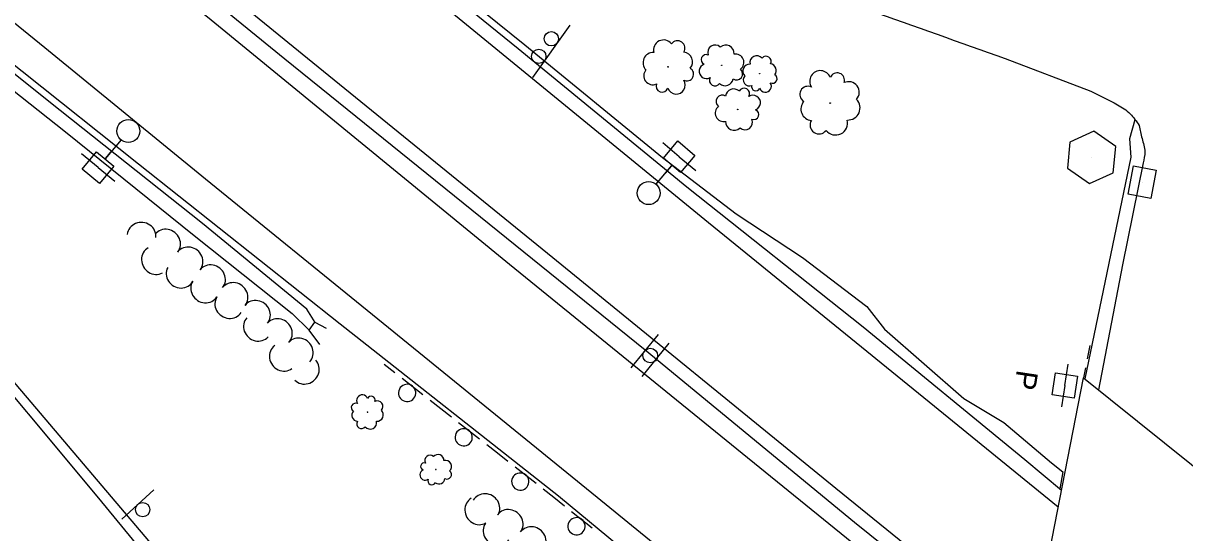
# Model space of a CAD drawing. Extents: x 1746010 to 1754829, y 655801 to 663091.
# Drawn here: x 1748666.3 to 1749070.2, y 661182.3 to 661359.7 of the extents above; entities that cross this region are included whole.
import ezdxf

# ---------------------------------------------------------------- set-up
doc = ezdxf.new("R2010")
doc.units = 0
for name, color, linetype in [('SURVEY - AERIAL SURVEY - Photo Control - Points - Elevations', 7, 'Continuous'), ('SURVEY - AERIAL SURVEY - Photo Control - Points - Locators', 7, 'Continuous'), ('SURVEY - AERIAL SURVEY - Photo Control - Points - Numbers', 7, 'Continuous'), ('SURVEY - AERIAL SURVEY - Photo Control with Text', 7, 'Continuous'), ('SURVEY - CENTERLINE - Existing Roads Curve Text', 7, 'Continuous'), ('SURVEY - CENTERLINE - Existing Roads Text', 7, 'Continuous'), ('SURVEY - CENTERLINE - Preliminary - Development', 7, 'Continuous')]:
    doc.layers.add(name, color=color, linetype=linetype)

msp = doc.modelspace()

# ---------------------------------------------------------------- linework, layer by layer
at = {"layer": 'SURVEY - AERIAL SURVEY - Photo Control - Points - Elevations'}
for points in [[(1748713.37, 661453.65), (1748716.55, 661453.81), (1748746.53, 661428.67), (1748797.36, 661387.23), (1748840.72, 661352.13), (1748888.64, 661312.91), (1748914.18, 661293.34), (1748937.25, 661278.19), (1748959.67, 661261.1), (1748965.83, 661253.19), (1748993.44, 661229.06), (1749007.32, 661220.73), (1749023.86, 661206.7), (1749027.85, 661203.6), (1749026.76, 661197.6)], [(1748767.81, 661255.54), (1748764.9, 661260.11), (1748728.66, 661289.97), (1748679.17, 661329.29), (1748636.92, 661363.04), (1748593.63, 661396.59), (1748567.91, 661416.28), (1748565.84, 661413.35), (1748621.69, 661369.01), (1748680.97, 661321.93), (1748725.75, 661285.75), (1748759.81, 661258.65), (1748765.74, 661252.81)], [(1748769.51, 661247.87), (1748765.74, 661252.81), (1748767.69, 661255.6), (1748771.63, 661253.55)], [(1749091.38, 661191), (1749050.62, 660981.19), (1748994.11, 661026.26), (1749035.04, 661236.3)], [(1749035.04, 661236.3), (1749091.38, 661191)]]:
    msp.add_lwpolyline(points, dxfattribs=at)
at = {"layer": 'SURVEY - AERIAL SURVEY - Photo Control - Points - Locators'}
for points in [[(1749014.37, 661130.26), (1748990.7, 661149.54), (1748916.31, 661209.97), (1748835.38, 661275.76), (1748731.71, 661360.72), (1748655.6, 661422.38), (1748555.07, 661504.4), (1748459.33, 661582.61), (1748380.29, 661646.59), (1748288.83, 661717.68), (1748181.12, 661800.02), (1748091.36, 661866.45), (1748036.84, 661905.72)], [(1749004.96, 661081.96), (1748990.07, 661094.14), (1748934.34, 661138.81), (1748865.88, 661194.6), (1748789.64, 661256.64), (1748729.69, 661305.4), (1748673.84, 661351.11), (1748595.91, 661414.43), (1748530.55, 661467.92), (1748473.83, 661514.17), (1748421, 661557.21), (1748361.81, 661604.95), (1748313.62, 661643.08), (1748341.85, 661611.66), (1748371.26, 661577.05), (1748408.51, 661529.92)], [(1749002.83, 661071), (1748965.52, 661101.51), (1748852.49, 661195.09), (1748776.59, 661254.93), (1748706.42, 661310.6), (1748625.44, 661375.29), (1748570.62, 661419.8), (1748495.86, 661480.71), (1748433.37, 661530.35), (1748414.07, 661545.49), (1748413.71, 661545.75)], [(1748406.97, 661541.06), (1748446.41, 661490.26), (1748508.74, 661414.72), (1748569.86, 661344.49), (1748590.82, 661319.8), (1748726.77, 661159.53), (1748751.93, 661128.01), (1748766.95, 661111.05), (1748766.91, 661110.24)], [(1748523.79, 661544.26), (1748587.7, 661492.34), (1748672.29, 661423.24), (1748765.2, 661347.55), (1748850.45, 661278.14), (1748948.94, 661197.9), (1749016.8, 661142.7)], [(1749026.26, 661191.27), (1748981.31, 661227.83), (1748904.63, 661290.22), (1748803.87, 661372.8), (1748715.15, 661444.7), (1748642.21, 661503.71), (1748667.72, 661487.53), (1748715.24, 661463.43)], [(1749027.39, 661197.07), (1749014.65, 661207.7), (1748958.39, 661253.89), (1748897.1, 661302.67), (1748838.46, 661350.81), (1748788.42, 661391.33), (1748735.2, 661434.76), (1748714.24, 661451.33), (1748713.32, 661453.39), (1748714.02, 661456.96), (1748716.26, 661459.11), (1748720.91, 661460.82)], [(1748543.22, 661365.16), (1748594.47, 661308.59), (1748642.89, 661253.78), (1748692.5, 661194.4), (1748742.62, 661133.3)], [(1749007.79, 661347.35), (1749037.51, 661336.03)], [(1749052.83, 661326.1), (1749050.99, 661319.39), (1749051.52, 661313.03), (1749035.46, 661235.96)], [(1749055.75, 661311.05), (1749048.62, 661275.6), (1749040.22, 661232.14)]]:
    msp.add_lwpolyline(points, dxfattribs=at)
for points in [[(1748715.24, 661463.43), (1748765.05, 661440.48), (1748816.14, 661417.66), (1748863.57, 661398.48), (1748914.39, 661379.98), (1748960.41, 661364.19), (1749007.79, 661347.35)], [(1749037.51, 661336.03), (1749046.79, 661331.31), (1749051.24, 661328.17), (1749054.38, 661324.09)], [(1749054.38, 661324.09), (1749055.37, 661319.56), (1749056.33, 661314.9), (1749055.75, 661311.05)]]:
    msp.add_spline(points, degree=3, dxfattribs=at)
at = {"layer": 'SURVEY - AERIAL SURVEY - Photo Control - Points - Numbers'}
for points in [[(1748040.01, 661910.33), (1748122.02, 661850.78), (1748195.38, 661796.53), (1748267.56, 661741.32), (1748333.52, 661690.82), (1748402.34, 661636.08), (1748451.04, 661597.23), (1748504.04, 661553.85), (1748559.78, 661508.8), (1748636.39, 661445.77), (1748709.27, 661386.44), (1748757.29, 661347.34), (1748822.35, 661294.7), (1748882.58, 661246), (1748955.33, 661186.03), (1749015.15, 661137.9)], [(1749037.18, 661247.5), (1749036.29, 661242.88)], [(1748791.87, 661241.03), (1748795.56, 661238.12)], [(1749035.69, 661239.74), (1749035.04, 661236.3)], [(1748798.08, 661236.15), (1748805.32, 661230.47)], [(1748807.83, 661228.49), (1748811.53, 661225.59)], [(1748811.53, 661225.59), (1748815.23, 661222.69)], [(1748817.74, 661220.71), (1748824.98, 661215.03)], [(1748827.5, 661213.06), (1748831.19, 661210.16)], [(1748831.19, 661210.16), (1748834.89, 661207.25)], [(1748837.41, 661205.28), (1748844.64, 661199.6)], [(1748847.16, 661197.62), (1748850.83, 661194.69)], [(1748850.83, 661194.69), (1748854.51, 661191.76)], [(1748857.01, 661189.77), (1748864.2, 661184.03)]]:
    msp.add_lwpolyline(points, dxfattribs=at)
for centre, start, end in [((1748799.82, 661231.01), 164.9095, 164.8956), ((1748819.49, 661215.57), 164.9095, 164.8956), ((1748839.15, 661200.14), 164.9095, 164.8956), ((1748858.71, 661184.61), 164.4875, 164.4736)]:
    msp.add_arc(centre, 3, start, end, dxfattribs=at)
at = {"layer": 'SURVEY - AERIAL SURVEY - Photo Control with Text'}
for p, q in [((1748856.42, 661359.05), (1748843.38, 661340.83)), ((1749037.77, 661312.94), (1749037.77, 661312.94)), ((1748877.78, 661239.73), (1748887.27, 661251.34)), ((1748881.5, 661236.69), (1748890.99, 661248.31)), ((1748700.64, 661187.12), (1748711.72, 661197.23))]:
    msp.add_line(p, q, dxfattribs=at)
msp.add_lwpolyline([(1749038.62, 661322.13), (1749030.25, 661318.24), (1749029.51, 661309.22), (1749037.11, 661303.86), (1749045.29, 661307.64), (1749046.22, 661316.77), (1749038.62, 661322.13)], dxfattribs=at)
for centre, radius in [((1748849.97, 661354.26), 2.5), ((1748845.61, 661348.15), 2.5), ((1748884.38, 661244.02), 2.54), ((1748707.86, 661190.39), 2.5)]:
    msp.add_circle(centre, radius, dxfattribs=at)
at = {"layer": 'SURVEY - CENTERLINE - Existing Roads Curve Text'}
for p, q in [((1748700.39, 661319.14), (1748694.85, 661312.43)), ((1748692.36, 661309.42), (1748686.58, 661314.2)), ((1748695.1, 661312.74), (1748697.14, 661315.21)), ((1748894.42, 661313.19), (1748888.68, 661318.01)), ((1748886.32, 661303.54), (1748891.91, 661310.2)), ((1748894.42, 661313.19), (1748900.17, 661308.37)), ((1748692.36, 661309.42), (1748698.15, 661304.65)), ((1748891.66, 661309.9), (1748889.6, 661307.45)), ((1749028.51, 661233.6), (1749029.63, 661241.02)), ((1749028.51, 661233.6), (1749027.38, 661226.19))]:
    msp.add_line(p, q, dxfattribs=at)
for points in [[(1748899.92, 661313.67), (1748894.9, 661307.69), (1748888.93, 661312.71), (1748893.94, 661318.69)], [(1748686.87, 661308.9), (1748691.84, 661314.92), (1748697.86, 661309.95), (1748692.89, 661303.93)], [(1749032.95, 661236.88), (1749031.78, 661229.16), (1749024.07, 661230.33), (1749025.24, 661238.04)]]:
    msp.add_lwpolyline(points, close=True, dxfattribs=at)
for centre in [(1748702.87, 661322.15), (1748883.81, 661300.55)]:
    msp.add_circle(centre, 4, dxfattribs=at)
at = {"layer": 'SURVEY - CENTERLINE - Existing Roads Text'}
for centre, radius in [((1748890.56, 661344.51), 0.109), ((1748909.23, 661345.03), 0.0891), ((1748922.44, 661342.08), 0.0734), ((1748946.94, 661331.89), 0.129), ((1748914.76, 661329.66), 0.0907), ((1748786.03, 661224.32), 0.0688), ((1748809.8, 661204.35), 0.0645)]:
    msp.add_circle(centre, radius, dxfattribs=at)
for centre, radius, start, end in [((1748888.98, 661350.33), 3.52, 38.1082, 193.9467), ((1748893.84, 661350.95), 2.6, 328.3611, 143.3613), ((1748906.9, 661349.56), 2.55, 45.0405, 201.8294), ((1748910.63, 661349.2), 2.91, 354.0933, 131.6175), ((1748885.39, 661345.94), 3.55, 87.2123, 224.7366), ((1748895.76, 661346.25), 3.35, 318.2022, 85.0478), ((1748903.84, 661347), 1.75, 67.1567, 245.9023), ((1748914.06, 661346.06), 2.89, 304.9891, 100.8276), ((1748921.37, 661346.01), 2.38, 38.1082, 193.9467), ((1748924.65, 661346.43), 1.76, 328.3611, 143.3613), ((1748885.19, 661341.37), 3.11, 138.1596, 294.9485), ((1748897.08, 661341.97), 2.36, 242.9151, 60.2343), ((1748903.88, 661342.96), 2.55, 107.1774, 300.5971), ((1748914.36, 661342.05), 2.13, 235.242, 50.2423), ((1748918.94, 661343.04), 2.4, 87.2123, 224.7366), ((1748925.95, 661343.26), 2.26, 318.2022, 85.0478), ((1748943.53, 661339.48), 3.7, 20.2964, 213.7161), ((1748949.37, 661339.85), 2.54, 340.2758, 159.0214), ((1748888.51, 661337.83), 2.14, 160.2758, 339.0214), ((1748893.42, 661338.14), 3.11, 200.2964, 33.7161), ((1748906.85, 661339.79), 1.94, 149.796, 327.1152), ((1748910.42, 661340.69), 2.75, 225.0831, 351.9288), ((1748918.81, 661339.96), 2.1, 138.1596, 294.9485), ((1748924.37, 661337.77), 2.1, 200.2964, 33.7161), ((1748926.85, 661340.36), 1.6, 242.9151, 60.2343), ((1748953.33, 661335.63), 3.71, 318.1596, 114.9485), ((1748909.41, 661332.46), 2.17, 57.8058, 232.806), ((1748913.35, 661334.02), 2.8, 47.6469, 174.4925), ((1748916.94, 661335.09), 1.97, 332.3598, 149.679), ((1748920.1, 661332.01), 2.59, 289.7411, 123.1608), ((1748921.05, 661337.56), 1.44, 160.2758, 339.0214), ((1748939.17, 661334.92), 2.81, 62.9151, 240.2343), ((1748909.89, 661328.39), 2.94, 127.5529, 283.3913), ((1748940.75, 661329.82), 3.99, 138.2022, 265.0478), ((1748953.1, 661330.2), 4.22, 267.2123, 44.7366), ((1748917.34, 661325.16), 2.6, 227.6043, 24.3932), ((1748920.32, 661327.91), 1.78, 249.7205, 68.4661), ((1748913.53, 661325.36), 2.96, 176.657, 314.1813), ((1748943.04, 661324.23), 3.09, 148.3611, 323.3613), ((1748948.82, 661324.97), 4.19, 218.1082, 13.9467), ((1748784.23, 661228.36), 1.97, 20.0207, 213.4404), ((1748787.34, 661228.54), 1.35, 340, 158.7457), ((1748781.91, 661225.95), 1.5, 62.6394, 239.9585), ((1748789.44, 661226.29), 1.97, 317.8839, 114.6728), ((1748782.73, 661223.23), 2.12, 137.9264, 264.7721), ((1748789.3, 661223.4), 2.25, 266.9366, 44.4608), ((1748783.93, 661220.25), 1.65, 148.0853, 323.0856), ((1748787.01, 661220.63), 2.23, 217.8324, 13.6709), ((1748807.8, 661207.45), 1.85, 50.618, 207.4069), ((1748810.51, 661207.45), 2.11, 359.6707, 137.1949), ((1748805.78, 661205.39), 1.27, 72.7341, 251.4798), ((1748813.2, 661205.44), 2.09, 310.5665, 106.405), ((1748806.09, 661202.49), 1.84, 112.7548, 306.1745), ((1748810.96, 661201.31), 1.99, 230.6605, 357.5062), ((1748813.7, 661202.57), 1.54, 240.8194, 55.8197), ((1748808.45, 661200.42), 1.4, 155.3735, 332.6926)]:
    msp.add_arc(centre, radius, start, end, dxfattribs=at)
for centre, major_axis in [((1748707.47, 661285.65), (4.97, -0.52)), ((1748716.12, 661283.15), (3.92, -3.11)), ((1748723.94, 661276.96), (3.92, -3.11)), ((1748712.24, 661277.16), (-2.46, 4.35)), ((1748720.95, 661272.3), (-4.39, 2.4)), ((1748731.75, 661270.76), (3.92, -3.11)), ((1748729.49, 661267.15), (-4.2, 2.71)), ((1748739.57, 661264.57), (3.92, -3.11)), ((1748737.88, 661261.74), (-4.2, 2.71)), ((1748747.39, 661258.37), (3.92, -3.11)), ((1748747.79, 661253.86), (-3.72, 3.34)), ((1748755.03, 661251.99), (3.66, -3.41)), ((1748762.3, 661245.24), (3.66, -3.41)), ((1748756.75, 661243.49), (-2.99, 4.01)), ((1748764.4, 661238.92), (-3.62, -3.45)), ((1748824.67, 661190.08), (-2.54, 4.31)), ((1748827.13, 661191.13), (4.33, -2.5)), ((1748835.27, 661185.62), (4, -3)), ((1748831.15, 661182.79), (-4.09, 2.88)), ((1748843.27, 661179.62), (4, -3))]:
    msp.add_ellipse(centre, major_axis=major_axis, ratio=0.940188, start_param=0, end_param=3.141593, dxfattribs=at)
at = {"layer": 'SURVEY - CENTERLINE - Preliminary - Development'}
msp.add_line((1749055.45, 661304.37), (1749055.45, 661304.37), dxfattribs=at)
msp.add_lwpolyline([(1749052.46, 661310.03), (1749060.31, 661308.53), (1749058.43, 661298.7), (1749050.58, 661300.21), (1749052.46, 661310.03)], dxfattribs=at)

# ---------------------------------------------------------------- texts
at = {"layer": 'SURVEY - CENTERLINE - Existing Roads Curve Text'}
msp.add_text('P', height=7.48, rotation=261.3919, dxfattribs=at).set_placement((1749011.86, 661239.26))

doc.saveas('drawing.dxf')
